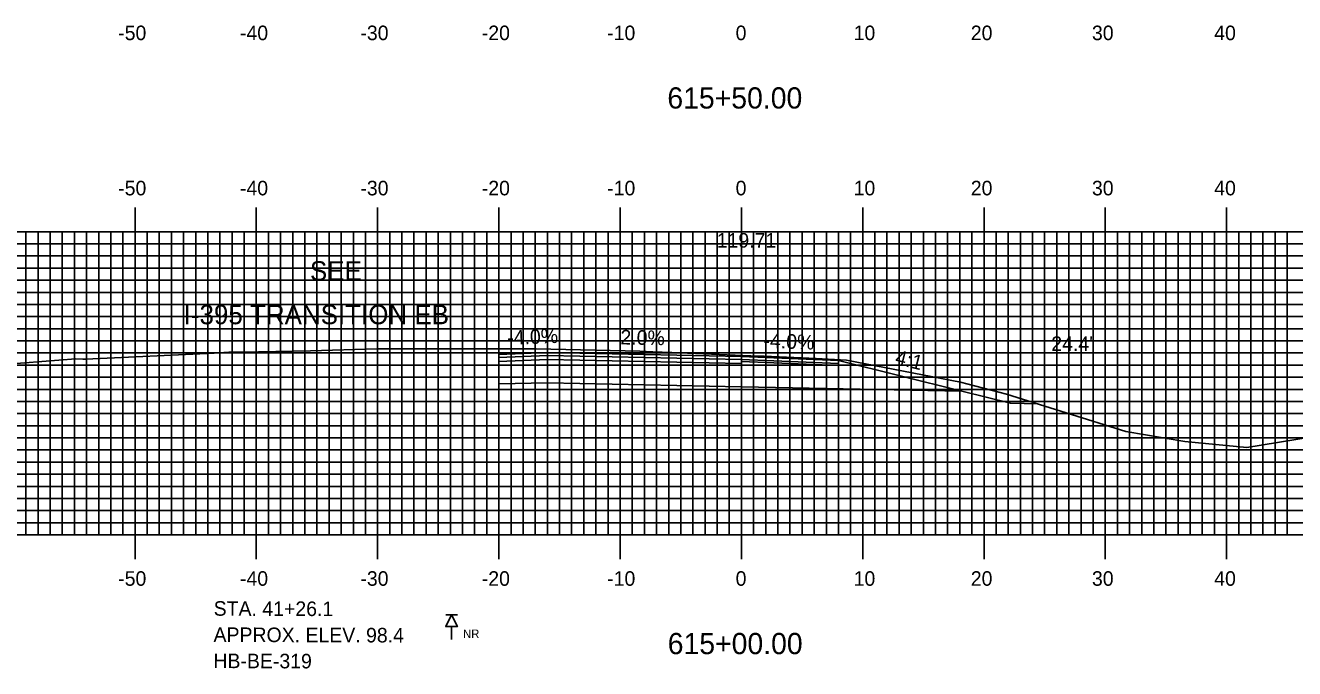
# Model space of a CAD drawing. Extents: x 844536 to 844879, y 363538 to 363758.
# Drawn here: x 844642.9 to 844747.6, y 363589.7 to 363642.7 of the extents above; entities that cross this region are included whole.
import ezdxf

# ---------------------------------------------------------------- set-up
doc = ezdxf.new("R2010")
doc.units = 0
for name, color, linetype in [('ANNOTATION', 7, 'Continuous'), ('BORING - NO REFUSAL', 7, 'Continuous'), ('D_Roadway_Centerline', 7, 'Continuous'), ('D_Roadway_Centerline_Text', 7, 'Continuous'), ('D_Roadway_Edge_Shoulder', 7, 'Continuous'), ('D_Roadway_Edge_TW', 7, 'Continuous'), ('D_Roadway_FinishedGrade', 7, 'Continuous'), ('D_Roadway_Pavement', 7, 'Continuous'), ('D_Roadway_SubGrade', 7, 'Continuous'), ('D_Text_Standard', 7, 'Continuous'), ('H_V ANNOTATION', 7, 'Continuous'), ('M_Roadway_Centerline', 7, 'Continuous'), ('MAJOR', 7, 'Continuous'), ('MINOR', 7, 'Continuous'), ('S_Roadway_Centerline', 7, 'Continuous')]:
    doc.layers.add(name, color=color, linetype=linetype)

msp = doc.modelspace()

# ---------------------------------------------------------------- linework, layer by layer
at = {"layer": 'BORING - NO REFUSAL'}
for p, q in [((844678.54, 363594.12), (844677.58, 363594.12)), ((844678.06, 363593.16), (844678.06, 363592.1))]:
    msp.add_line(p, q, dxfattribs=at)
msp.add_lwpolyline([(844678.06, 363594.12), (844678.54, 363593.16), (844677.58, 363593.16)], close=True, dxfattribs=at)
at = {"layer": 'D_Roadway_Centerline'}
msp.add_lwpolyline([(844681.96, 363615.59), (844685.96, 363615.75), (844701.96, 363615.43), (844709.96, 363615.11), (844720.14, 363612.57)], dxfattribs=at)
at = {"layer": 'D_Roadway_Edge_Shoulder'}
for points in [[(844685.96, 363615.75), (844681.96, 363615.59), (844681.96, 363615.34), (844685.96, 363615.5)], [(844701.96, 363615.43), (844709.96, 363615.11), (844709.96, 363614.86), (844701.96, 363615.18)]]:
    msp.add_lwpolyline(points, close=True, dxfattribs=at)
at = {"layer": 'D_Roadway_Edge_TW'}
msp.add_lwpolyline([(844685.96, 363615.75), (844701.96, 363615.43), (844701.96, 363615.18), (844685.96, 363615.5)], close=True, dxfattribs=at)
at = {"layer": 'D_Roadway_FinishedGrade'}
msp.add_lwpolyline([(844720.14, 363612.57), (844724.14, 363611.57), (844726.4, 363611.52)], dxfattribs=at)
at = {"layer": 'D_Roadway_Pavement'}
for points in [[(844685.96, 363615.5), (844681.96, 363615.34), (844681.96, 363615.01), (844685.96, 363615.17)], [(844685.96, 363615.5), (844701.96, 363615.18), (844701.96, 363614.85), (844685.96, 363615.17)], [(844701.96, 363615.18), (844709.96, 363614.86), (844709.96, 363614.7), (844701.96, 363615.02)]]:
    msp.add_lwpolyline(points, close=True, dxfattribs=at)
msp.add_lwpolyline([(844701.96, 363615.18), (844701.96, 363614.85)], dxfattribs=at)
msp.add_lwpolyline([(844701.96, 363615.18), (844701.96, 363614.85)], dxfattribs=at)
at = {"layer": 'D_Roadway_SubGrade'}
msp.add_line((844681.96, 363624.27), (844681.96, 363613.17), dxfattribs=at)
for points in [[(844685.96, 363615.17), (844681.96, 363615.01), (844681.96, 363615.34), (844681.96, 363615.59), (844681.96, 363613.17), (844685.96, 363613.25)], [(844685.96, 363615.17), (844701.96, 363614.85), (844701.96, 363612.93), (844685.96, 363613.25)], [(844701.96, 363614.85), (844701.96, 363615.18), (844709.96, 363614.86), (844709.96, 363615.11), (844720.14, 363612.57), (844701.96, 363612.93)]]:
    msp.add_lwpolyline(points, close=True, dxfattribs=at)
at = {"layer": 'MAJOR'}
for p, q in [((844651.96, 363627.73), (844651.96, 363625.72)), ((844661.96, 363627.73), (844661.96, 363625.72)), ((844671.96, 363627.73), (844671.96, 363625.72)), ((844681.96, 363627.73), (844681.96, 363625.72)), ((844691.96, 363627.73), (844691.96, 363625.72)), ((844701.96, 363627.73), (844701.96, 363625.72)), ((844711.96, 363627.73), (844711.96, 363625.72)), ((844721.96, 363627.73), (844721.96, 363625.72)), ((844731.96, 363627.73), (844731.96, 363625.72)), ((844741.96, 363627.73), (844741.96, 363625.72)), ((844561.96, 363625.72), (844841.96, 363625.72)), ((844561.96, 363625.72), (844841.96, 363625.72)), ((844651.96, 363600.72), (844651.96, 363625.72)), ((844661.96, 363600.72), (844661.96, 363625.72)), ((844671.96, 363600.72), (844671.96, 363625.72)), ((844681.96, 363600.72), (844681.96, 363625.72)), ((844691.96, 363600.72), (844691.96, 363625.72)), ((844701.96, 363600.72), (844701.96, 363625.72)), ((844711.96, 363600.72), (844711.96, 363625.72)), ((844721.96, 363600.72), (844721.96, 363625.72)), ((844731.96, 363600.72), (844731.96, 363625.72)), ((844741.96, 363600.72), (844741.96, 363625.72)), ((844561.96, 363620.72), (844841.96, 363620.72)), ((844561.96, 363615.72), (844841.96, 363615.72)), ((844561.96, 363610.72), (844841.96, 363610.72)), ((844561.96, 363605.72), (844841.96, 363605.72)), ((844561.96, 363600.72), (844841.96, 363600.72)), ((844561.96, 363600.72), (844841.96, 363600.72)), ((844651.96, 363598.72), (844651.96, 363600.72)), ((844661.96, 363598.72), (844661.96, 363600.72)), ((844671.96, 363598.72), (844671.96, 363600.72)), ((844681.96, 363598.72), (844681.96, 363600.72)), ((844691.96, 363598.72), (844691.96, 363600.72)), ((844701.96, 363598.72), (844701.96, 363600.72)), ((844711.96, 363598.72), (844711.96, 363600.72)), ((844721.96, 363598.72), (844721.96, 363600.72)), ((844731.96, 363598.72), (844731.96, 363600.72)), ((844741.96, 363598.72), (844741.96, 363600.72))]:
    msp.add_line(p, q, dxfattribs=at)
at = {"layer": 'MINOR'}
for p, q in [((844642.96, 363600.72), (844642.96, 363625.72)), ((844643.96, 363600.72), (844643.96, 363625.72)), ((844644.96, 363600.72), (844644.96, 363625.72)), ((844645.96, 363600.72), (844645.96, 363625.72)), ((844646.96, 363600.72), (844646.96, 363625.72)), ((844647.96, 363600.72), (844647.96, 363625.72)), ((844648.96, 363600.72), (844648.96, 363625.72)), ((844649.96, 363600.72), (844649.96, 363625.72)), ((844650.96, 363600.72), (844650.96, 363625.72)), ((844652.96, 363600.72), (844652.96, 363625.72)), ((844653.96, 363600.72), (844653.96, 363625.72)), ((844654.96, 363600.72), (844654.96, 363625.72)), ((844655.96, 363600.72), (844655.96, 363625.72)), ((844656.96, 363600.72), (844656.96, 363625.72)), ((844657.96, 363600.72), (844657.96, 363625.72)), ((844658.96, 363600.72), (844658.96, 363625.72)), ((844659.96, 363600.72), (844659.96, 363625.72)), ((844660.96, 363600.72), (844660.96, 363625.72)), ((844662.96, 363600.72), (844662.96, 363625.72)), ((844663.96, 363600.72), (844663.96, 363625.72)), ((844664.96, 363600.72), (844664.96, 363625.72)), ((844665.96, 363600.72), (844665.96, 363625.72)), ((844666.96, 363600.72), (844666.96, 363625.72)), ((844667.96, 363600.72), (844667.96, 363625.72)), ((844668.96, 363600.72), (844668.96, 363625.72)), ((844669.96, 363600.72), (844669.96, 363625.72)), ((844670.96, 363600.72), (844670.96, 363625.72)), ((844672.96, 363600.72), (844672.96, 363625.72)), ((844673.96, 363600.72), (844673.96, 363625.72)), ((844674.96, 363600.72), (844674.96, 363625.72)), ((844675.96, 363600.72), (844675.96, 363625.72)), ((844676.96, 363600.72), (844676.96, 363625.72)), ((844677.96, 363600.72), (844677.96, 363625.72)), ((844678.96, 363600.72), (844678.96, 363625.72)), ((844679.96, 363600.72), (844679.96, 363625.72)), ((844680.96, 363600.72), (844680.96, 363625.72)), ((844682.96, 363600.72), (844682.96, 363625.72)), ((844683.96, 363600.72), (844683.96, 363625.72)), ((844684.96, 363600.72), (844684.96, 363625.72)), ((844685.96, 363600.72), (844685.96, 363625.72)), ((844686.96, 363600.72), (844686.96, 363625.72)), ((844687.96, 363600.72), (844687.96, 363625.72)), ((844688.96, 363600.72), (844688.96, 363625.72)), ((844689.96, 363600.72), (844689.96, 363625.72)), ((844690.96, 363600.72), (844690.96, 363625.72)), ((844692.96, 363600.72), (844692.96, 363625.72)), ((844693.96, 363600.72), (844693.96, 363625.72)), ((844694.96, 363600.72), (844694.96, 363625.72)), ((844695.96, 363600.72), (844695.96, 363625.72)), ((844696.96, 363600.72), (844696.96, 363625.72)), ((844697.96, 363600.72), (844697.96, 363625.72)), ((844698.96, 363600.72), (844698.96, 363625.72)), ((844699.96, 363600.72), (844699.96, 363625.72)), ((844700.96, 363600.72), (844700.96, 363625.72)), ((844702.96, 363600.72), (844702.96, 363625.72)), ((844703.96, 363600.72), (844703.96, 363625.72)), ((844704.96, 363600.72), (844704.96, 363625.72)), ((844705.96, 363600.72), (844705.96, 363625.72)), ((844706.96, 363600.72), (844706.96, 363625.72)), ((844707.96, 363600.72), (844707.96, 363625.72)), ((844708.96, 363600.72), (844708.96, 363625.72)), ((844709.96, 363600.72), (844709.96, 363625.72)), ((844710.96, 363600.72), (844710.96, 363625.72)), ((844712.96, 363600.72), (844712.96, 363625.72)), ((844713.96, 363600.72), (844713.96, 363625.72)), ((844714.96, 363600.72), (844714.96, 363625.72)), ((844715.96, 363600.72), (844715.96, 363625.72)), ((844716.96, 363600.72), (844716.96, 363625.72)), ((844717.96, 363600.72), (844717.96, 363625.72)), ((844718.96, 363600.72), (844718.96, 363625.72)), ((844719.96, 363600.72), (844719.96, 363625.72)), ((844720.96, 363600.72), (844720.96, 363625.72)), ((844722.96, 363600.72), (844722.96, 363625.72)), ((844723.96, 363600.72), (844723.96, 363625.72)), ((844724.96, 363600.72), (844724.96, 363625.72)), ((844725.96, 363600.72), (844725.96, 363625.72)), ((844726.96, 363600.72), (844726.96, 363625.72)), ((844727.96, 363600.72), (844727.96, 363625.72)), ((844728.96, 363600.72), (844728.96, 363625.72)), ((844729.96, 363600.72), (844729.96, 363625.72)), ((844730.96, 363600.72), (844730.96, 363625.72)), ((844732.96, 363600.72), (844732.96, 363625.72)), ((844733.96, 363600.72), (844733.96, 363625.72)), ((844734.96, 363600.72), (844734.96, 363625.72)), ((844735.96, 363600.72), (844735.96, 363625.72)), ((844736.96, 363600.72), (844736.96, 363625.72)), ((844737.96, 363600.72), (844737.96, 363625.72)), ((844738.96, 363600.72), (844738.96, 363625.72)), ((844739.96, 363600.72), (844739.96, 363625.72)), ((844740.96, 363600.72), (844740.96, 363625.72)), ((844742.96, 363600.72), (844742.96, 363625.72)), ((844743.96, 363600.72), (844743.96, 363625.72)), ((844744.96, 363600.72), (844744.96, 363625.72)), ((844745.96, 363600.72), (844745.96, 363625.72)), ((844746.96, 363600.72), (844746.96, 363625.72)), ((844561.96, 363624.72), (844841.96, 363624.72)), ((844561.96, 363623.72), (844841.96, 363623.72)), ((844561.96, 363622.72), (844841.96, 363622.72)), ((844561.96, 363621.72), (844841.96, 363621.72)), ((844561.96, 363619.72), (844841.96, 363619.72)), ((844561.96, 363618.72), (844841.96, 363618.72)), ((844561.96, 363617.72), (844841.96, 363617.72)), ((844561.96, 363616.72), (844841.96, 363616.72)), ((844561.96, 363614.72), (844841.96, 363614.72)), ((844561.96, 363613.72), (844841.96, 363613.72)), ((844561.96, 363612.72), (844841.96, 363612.72)), ((844561.96, 363611.72), (844841.96, 363611.72)), ((844561.96, 363609.72), (844841.96, 363609.72)), ((844561.96, 363608.72), (844841.96, 363608.72)), ((844561.96, 363607.72), (844841.96, 363607.72)), ((844561.96, 363606.72), (844841.96, 363606.72)), ((844561.96, 363604.72), (844841.96, 363604.72)), ((844561.96, 363603.72), (844841.96, 363603.72)), ((844561.96, 363602.72), (844841.96, 363602.72)), ((844561.96, 363601.72), (844841.96, 363601.72))]:
    msp.add_line(p, q, dxfattribs=at)
at = {"layer": 'S_Roadway_Centerline'}
msp.add_lwpolyline([(844641.46, 363614.79), (844647.09, 363615.24), (844647.65, 363615.21), (844647.91, 363615.22), (844658.49, 363615.7), (844659.68, 363615.78), (844660.7, 363615.78), (844666.42, 363615.91), (844671.9, 363616.06), (844681.99, 363616.06), (844685.02, 363616.05), (844693.59, 363615.86), (844694.64, 363615.82), (844696.21, 363615.77), (844702.73, 363615.49), (844703.84, 363615.45), (844708.12, 363615.26), (844710.62, 363615.13), (844720.01, 363613.31), (844723.81, 363612.33), (844733.66, 363609.25), (844738.52, 363608.42), (844743.63, 363607.93), (844754.24, 363609.66)], dxfattribs=at)

# ---------------------------------------------------------------- texts
at = {"layer": 'ANNOTATION'}
for s, p in [('SEE', (844666.38, 363621.69)), ('I-395 TRANSITION EB', (844655.97, 363618.09))]:
    msp.add_text(s, height=1.6, dxfattribs=at).set_placement(p)
for s, rotation, p in [('-4.0%', 2.2906, (844682.67, 363616.38)), ('2.0%', 358.8542, (844691.97, 363616.43)), ('-4.0%', 357.7094, (844703.76, 363616.16)), ('4:1', 345.9638, (844714.56, 363614.83))]:
    msp.add_text(s, height=1.2, rotation=rotation, dxfattribs=at).set_placement(p)
at = {"layer": 'BORING - NO REFUSAL'}
for s, p in [('STA. 41+26.1', (844658.44, 363594.05)), ('APPROX. ELEV. 98.4', (844658.43, 363591.89)), ('HB-BE-319', (844658.42, 363589.73))]:
    msp.add_text(s, height=1.2, rotation=359.8142, dxfattribs=at).set_placement(p)
msp.add_text('NR', height=0.7, dxfattribs=at).set_placement((844679, 363592.21))
at = {"layer": 'D_Roadway_Centerline_Text'}
msp.add_text('119.71', height=1.2, dxfattribs=at).set_placement((844699.92, 363624.41))
at = {"layer": 'D_Text_Standard'}
msp.add_text("24.4'", height=1.2, dxfattribs=at).set_placement((844727.51, 363615.89))
at = {"layer": 'H_V ANNOTATION'}
for s, height, p in [('-50', 1.2, (844650.57, 363641.52)), ('-40', 1.2, (844660.61, 363641.52)), ('-30', 1.2, (844670.54, 363641.52)), ('-20', 1.2, (844680.55, 363641.52)), ('-10', 1.2, (844690.89, 363641.52)), ('0', 1.2, (844701.48, 363641.52)), ('10', 1.2, (844711.21, 363641.52)), ('20', 1.2, (844720.87, 363641.52)), ('30', 1.2, (844730.86, 363641.52)), ('40', 1.2, (844740.94, 363641.52)), ('615+50.00', 1.75, (844695.85, 363635.88)), ('-50', 1.2, (844650.57, 363628.72)), ('-40', 1.2, (844660.61, 363628.72)), ('-30', 1.2, (844670.54, 363628.72)), ('-20', 1.2, (844680.55, 363628.72)), ('-10', 1.2, (844690.89, 363628.72)), ('0', 1.2, (844701.48, 363628.72)), ('10', 1.2, (844711.21, 363628.72)), ('20', 1.2, (844720.87, 363628.72)), ('30', 1.2, (844730.86, 363628.72)), ('40', 1.2, (844740.94, 363628.72)), ('-50', 1.2, (844650.57, 363596.52)), ('-40', 1.2, (844660.61, 363596.52)), ('-30', 1.2, (844670.54, 363596.52)), ('-20', 1.2, (844680.55, 363596.52)), ('-10', 1.2, (844690.89, 363596.52)), ('0', 1.2, (844701.48, 363596.52)), ('10', 1.2, (844711.21, 363596.52)), ('20', 1.2, (844720.87, 363596.52)), ('30', 1.2, (844730.86, 363596.52)), ('40', 1.2, (844740.94, 363596.52)), ('615+00.00', 1.75, (844695.88, 363590.88))]:
    msp.add_text(s, height=height, dxfattribs=at).set_placement(p)
at = {"layer": 'M_Roadway_Centerline'}
for s, p in [('C', (844659.68, 363615.78)), ('L', (844659.68, 363615.77)), ('C', (844694.63, 363615.82)), ('L', (844694.64, 363615.81))]:
    msp.add_text(s, height=0.0146, dxfattribs=at).set_placement(p)

doc.saveas('drawing.dxf')
